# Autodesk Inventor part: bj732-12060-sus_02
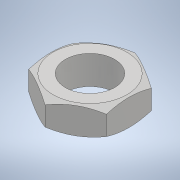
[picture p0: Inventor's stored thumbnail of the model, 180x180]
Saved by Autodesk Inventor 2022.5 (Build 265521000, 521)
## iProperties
Part Number: bj732-12060-sus_02
Material: 一般
Document SubType Name: Modeling
Designer: ImaoCorp
Density: 1 g/cm^3
Appearance: 既定
Author: ImaoCorp
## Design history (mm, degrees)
feature "bj732-12060-sus_02"
node "ソリッド1"
